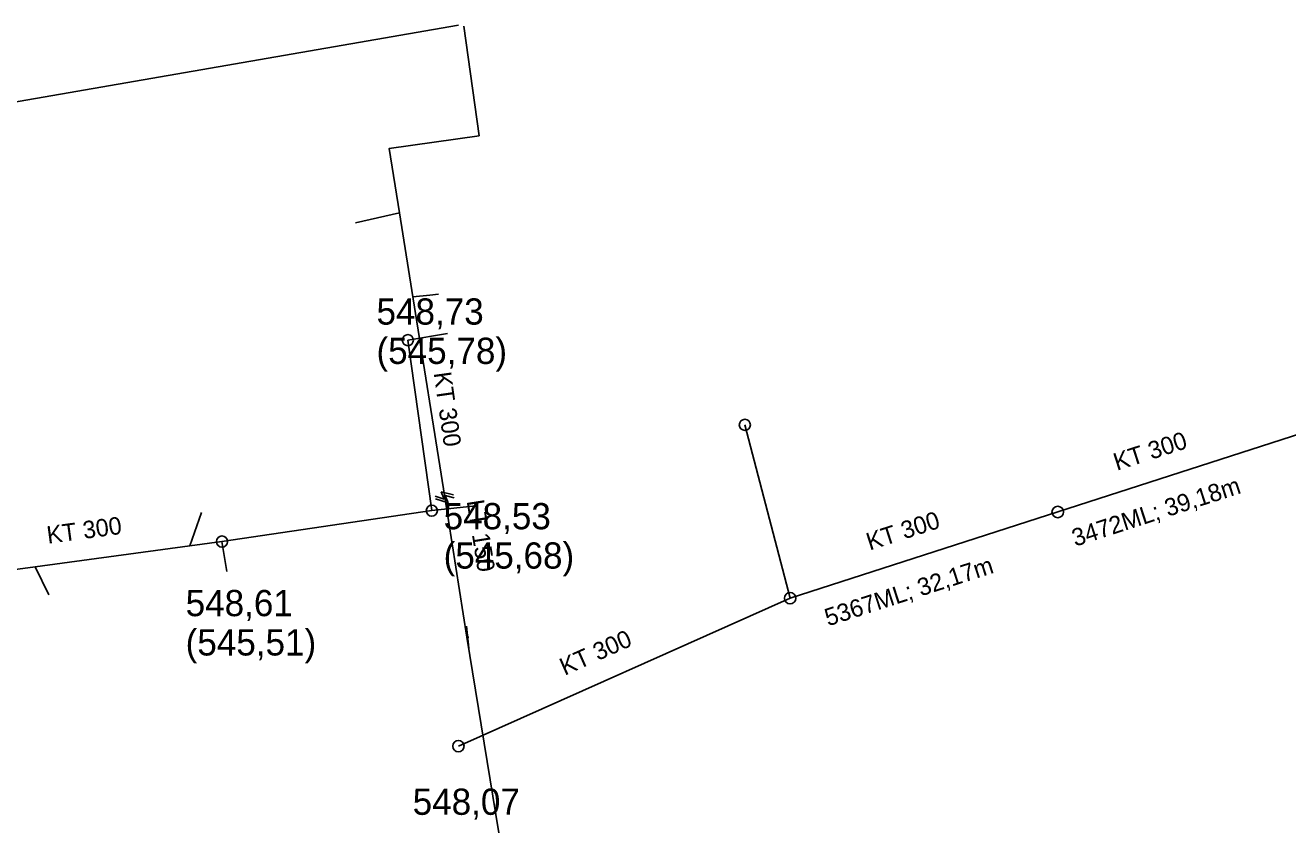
# Model space of a CAD drawing. Extents: x -867696 to -865033, y -1042522 to -1039817.
# Drawn here: x -866140.2 to -865995.7, y -1040061.2 to -1039969.7 of the extents above; entities that cross this region are included whole.
import ezdxf

# ---------------------------------------------------------------- set-up
doc = ezdxf.new("R2010")
doc.units = 0
for name, color, linetype in [('KN - jednotna', 7, 'Continuous'), ('KN - popis material', 7, 'Continuous'), ('KN - popis ostatni', 7, 'Continuous'), ('KN - popis usek delka', 7, 'Continuous'), ('KN - pripojka', 7, 'Continuous'), ('KN - sachta komora', 7, 'Continuous'), ('Level 1', 7, 'Continuous'), ('V - hydrant', 7, 'Continuous'), ('V - ostatni', 7, 'Continuous'), ('V - popis material', 7, 'Continuous'), ('V - pripojka', 7, 'Continuous'), ('V - rozvadeci', 7, 'Continuous')]:
    doc.layers.add(name, color=color, linetype=linetype)

# ---------------------------------------------------------------- blocks, each defined once
blk = doc.blocks.new('100.M')
at = {"layer": 'Level 1'}
blk.add_circle((0, 0), 1.27, dxfattribs=at)
blk = doc.blocks.new('156')
at = {"layer": 'Level 1'}
for p, q in [((-0.07, 1.04), (-0.68, -0.3)), ((0.28, 1.04), (-0.19, 0.08)), ((-0.19, 0.08), (0.7, 0.29)), ((0.7, 0.29), (0.02, -1.08)), ((-0.68, -0.3), (0.21, -0.09)), ((0.21, -0.09), (-0.28, -1.08))]:
    blk.add_line(p, q, dxfattribs=at)
blk = doc.blocks.new('150')
at = {"layer": 'Level 1'}
blk.add_line((0, 1.27), (0, -1.27), dxfattribs=at)

msp = doc.modelspace()

# ---------------------------------------------------------------- linework, layer by layer
at = {"layer": 'KN - jednotna'}
for points in [[(-866093.686, -1040025.293), (-866096.426, -1040005.784)], [(-865984.776, -1040013.42), (-866022.068, -1040025.442)], [(-866052.69, -1040035.313), (-866057.868, -1040015.475)], [(-866117.694, -1040028.827), (-866093.686, -1040025.293)], [(-866022.068, -1040025.442), (-866052.69, -1040035.313)], [(-866149.932, -1040033.166), (-866139.087, -1040031.706), (-866121.369, -1040029.322), (-866117.694, -1040028.827)], [(-866052.69, -1040035.313), (-866090.637, -1040052.239)]]:
    msp.add_lwpolyline(points, dxfattribs=at)
at = {"layer": 'KN - pripojka'}
for points in [[(-866096.426, -1040005.784), (-866091.908, -1040005.035)], [(-866093.686, -1040025.293), (-866088.633, -1040024.754)], [(-866121.369, -1040029.322), (-866120.05, -1040025.508)], [(-866117.694, -1040028.827), (-866117.133, -1040032.254)], [(-866139.087, -1040031.706), (-866137.504, -1040034.94)]]:
    msp.add_lwpolyline(points, dxfattribs=at)
at = {"layer": 'V - pripojka'}
for points in [[(-866097.381, -1039991.196), (-866102.405, -1039992.362)], [(-866095.843, -1040000.841), (-866093.908, -1040000.622), (-866092.902, -1040000.513)], [(-866089.664, -1040039.775), (-866089.439, -1040039.758)]]:
    msp.add_lwpolyline(points, dxfattribs=at)
at = {"layer": 'V - rozvadeci'}
for points in [[(-866090.65, -1039969.748), (-866141.906, -1039978.607), (-866154.816, -1039980.838)], [(-866090.006, -1039969.86), (-866088.268, -1039982.393), (-866098.553, -1039983.847), (-866097.381, -1039991.196), (-866095.963, -1040000.083), (-866092.208, -1040023.741), (-866089.664, -1040039.775), (-866085.38, -1040066.144)]]:
    msp.add_lwpolyline(points, dxfattribs=at)

# ---------------------------------------------------------------- block references
at = {"layer": 'KN - sachta komora'}
for p, xscale, yscale, rotation in [((-866096.426, -1040005.784), 0.49999999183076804, 0.49999999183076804, 98.00000038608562), ((-866057.868, -1040015.475), 0.499999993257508, 0.4999999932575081, 105.00000012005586), ((-866093.686, -1040025.293), 0.5000000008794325, 0.5000000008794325, 54.00000066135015), ((-866022.068, -1040025.442), 0.516753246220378, 0.516753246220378, 23.041281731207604), ((-866117.694, -1040028.827), 0.5041888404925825, 0.5041888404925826, -168.37362119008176), ((-866052.69, -1040035.313), 0.5137536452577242, 0.513753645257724, -155.31089431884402), ((-866090.637, -1040052.239), 0.5084781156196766, 0.5084781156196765, -153.02398354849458)]:
    msp.add_blockref('100.M', p, dxfattribs=dict(at, xscale=xscale, yscale=yscale, rotation=rotation))
at = {"layer": 'V - hydrant', "xscale": 1.0018265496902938, "yscale": 1.0018265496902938, "rotation": 6.078126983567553}
msp.add_blockref('150', (-866089.577, -1040039.768), dxfattribs=at)
at = {"layer": 'V - ostatni', "xscale": 0.9999999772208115, "yscale": 0.9999999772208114, "rotation": -79.99999971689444}
msp.add_blockref('156', (-866092.208, -1040023.741), dxfattribs=at)

# ---------------------------------------------------------------- texts
at = {"layer": 'KN - popis material'}
for rotation, p in [(277.99, (-866093.474, -1040009.541)), (17.87, (-866015.301, -1040020.739)), (7.66, (-866137.607, -1040029.084)), (17.87, (-866043.584, -1040029.856)), (24.04, (-866078.487, -1040044.192))]:
    msp.add_text('KT 300', height=2, rotation=rotation, dxfattribs=at).set_placement(p)
at = {"layer": 'KN - popis ostatni'}
for s, p in [('548,73 ', (-866100.016, -1040004.004)), ('(545,78)', (-866100.016, -1040008.504)), ('548,53 ', (-866092.336, -1040027.423)), ('(545,68)', (-866092.336, -1040031.923)), ('548,61 ', (-866121.854, -1040037.367)), ('(545,51)', (-866121.854, -1040041.867)), ('548,07 ', (-866095.877, -1040060.099))]:
    msp.add_text(s, height=3, dxfattribs=at).set_placement(p)
at = {"layer": 'KN - popis usek delka'}
for s, p in [('3472ML; 39,18m', (-866020.068, -1040029.421)), ('5367ML; 32,17m', (-866048.35, -1040038.538))]:
    msp.add_text(s, height=1.99999, rotation=17.87, dxfattribs=at).set_placement(p)
at = {"layer": 'V - popis material'}
msp.add_text('LT 150', height=2, rotation=279.02, dxfattribs=at).set_placement((-866089.707, -1040024.194))

doc.saveas('drawing.dxf')
